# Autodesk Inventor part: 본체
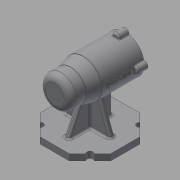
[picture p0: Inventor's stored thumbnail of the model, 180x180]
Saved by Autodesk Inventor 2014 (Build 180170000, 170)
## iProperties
Created: 2019-12
Part Number: 본체
Material: Aluminum 6061
Document SubType Name: Modeling
Designer: kh
Density: 2.71 g/cm^3
Appearance: Default
Mass: 727.794 g
Surface Area: 716.602 cm^2
Volume: 268.559 cm^3
Author: kh
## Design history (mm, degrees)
sketch "Sketch2"
  geometry: L1 (-56, 0)-(56, 0); L2 (-11, 30)-(56, 30); L3 (-56, 25)-(-31, 25); L4 (-31, 25)-(-11, 30); L5 (-56, 25)-(-56, 0); L6 (-13, 24)-(41, 24); L7 (41, 21)-(56, 21); L8 (41, 21)-(41, 24); L9 (56, 21)-(56, 30); L10 (-13, 21)-(-25, 21); L11 (-13, 21)-(-13, 24); L12 (-25, 17.5)-(-43, 17.5); L13 (-25, 17.5)-(-25, 21); L14 (-43, 16)-(-47, 16); L15 (-43, 16)-(-43, 17.5); L16 (-47, 10.5)-(-50, 10.5); L17 (-47, 10.5)-(-47, 16); L18 (-50, 10.5)-(-50, 0); 2 further points
  constraints: 36 end point, 12 perpendicular, 8 vertical alignment, 4 parallel, 2 coincident, 1 horizontal, 1 midpoint, 1 point on line
  dimensions: "d0" = 112 distance of L1.start L1.end; "d1" = 67 distance of L2.start L2.end; "d2" = 60 diameter of L2 L1; "d3" = 25 distance of L3.start L3.end; "d4" = 50 diameter of L3 L1; "d5" = 54 distance of L6.start L6.end; "d6" = 48 diameter of L6 L1; "d7" = 15 distance of L7.start L7.end; "d8" = 42 diameter of L7 L1; "d9" = 12 distance of L10.start L10.end; "d10" = 42 diameter of L10 L1; "d11" = 18 distance of L12.start L12.end; "d12" = 35 diameter of L12 L1; "d14" = 4 distance of L14.start L14.end; "d15" = 32 diameter of L14 L1; "d16" = 3 distance of L16.start L16.end; "d17" = 21 diameter of L16 L1
revolve "Revolution1" sketch "Sketch2" stored, may be unused: angle "d19" = 90 deg
fillet "Fillet1" dims "d22" = 3, "d23" = 0.3
workplane "Work Plane1"
sketch "Sketch4"
  geometry: L1 (0, 0)-(0, 30); C1 r 21 at (0, 0) reference; C2 r 6 at (0, 30); 1 further point
  constraints: 2 end point, 1 centre point, 1 coincident, 1 vertical, 1 vertical alignment, 1 other
  dimensions: "d24" = 12 diameter of C2
extrude "Extrusion2" join sketch "Sketch4" distance "d25" = 16; taper "d26" = 0 deg
fillet "Fillet2" dims "d27" = 3
fillet "Fillet3" dims "d28" = 1
pattern_circular "Circular Pattern1" dims "d30" = 360 deg
hole "Hole1" diameter "d34" = 3.242; stored, may be unused: countersink angle "d38" = 90 deg, drill point angle "d40" = 118 deg; dims "d32" = 10, "d33" = 10, "d35" = 8, "d36" = 4, "d37" = 2, "d39" = 11
pattern_circular "Circular Pattern2" dims angle "d42" = 360 deg
workplane "Work Plane2"
sketch "Sketch5"
  geometry: L1 (-6.771, 56)-(-29.226, 56) reference; L2 (29.226, 56)-(6.771, 56) reference; L3 (23.196, 56)-(56, 23.196); L4 (56, 23.196)-(56, -23.196); L5 (56, -23.196)-(23.196, -56); L6 (23.196, -56)-(-23.196, -56); L7 (-23.196, -56)-(-56, -23.196); L8 (-56, -23.196)-(-56, 23.196); L9 (-56, 23.196)-(-23.196, 56); L10 (-23.196, 56)-(23.196, 56); 2 further points
  constraints: 16 end point, 1 coincident, 1 collinear, 1 horizontal, 17 other
extrude "Extrusion3" join sketch "Sketch5" distance "d45" = 10; taper "d46" = 0 deg
sketch "Sketch6"
  geometry: L1 (56, 23.196)-(23.196, 56) reference; L2 (56, -23.196)-(56, 23.196) reference; L3 (0, 0)-(56, 0); L4 (0, 0)-(39.598, 39.598); C1 r 5 at (39.598, 39.598)
  constraints: 4 end point, 2 midpoint, 1 centre point, 1 coincident, 1 perpendicular
  dimensions: "d47" = 10 diameter of C1
extrude "Extrusion4" cut sketch "Sketch6" stored distance "d48" = 10; taper "d49" = 0 deg
pattern_circular "Circular Pattern3" dims angle "d51" = 360 deg
sketch "Sketch7"
  geometry: L1 (-56, -80)-(-56, -70) reference; L2 (56, -80)-(56, -70) reference; L3 (56, -70)-(43.134, -70) reference; L4 (23.196, -70)-(-23.196, -70) reference; L5 (-43.134, -70)-(-56, -70) reference; L6 (34.598, -70)-(43.134, -70) reference; L7 (36.062, -70)-(23.196, -70) reference; L8 (-43.134, -70)-(-34.598, -70) reference; L9 (-23.196, -70)-(-36.062, -70) reference; L10 (0, 0)-(0, -70); L11 (-36, -70)-(-18.979, -23.234); L12 (36, -70)-(18.979, -23.234); L13 (-36, -70)-(36, -70); A1 r 30 centre (0, 0) between (-18.979, -23.234) and (18.979, -23.234); 1 further point
  constraints: 8 end point, 2 point on circle, 2 symmetric about line, 1 centre point, 1 coincident, 1 collinear, 1 midpoint, 1 point on line, 2 other
  dimensions: "d55" = 110 deg angle of L5 L11; "d56" = 20 distance from line of L11.start L1
extrude "Extrusion5" join sketch "Sketch7" stored distance "d57" = 8; taper "d58" = 0 deg
sketch "Sketch8"
  geometry: L1 (-56, -80)-(-56, -70) reference; L2 (56, -80)-(56, -70) reference; L3 (56, -70)-(43.134, -70) reference; L4 (34.598, -70)-(43.134, -70) reference; L5 (36.062, -70)-(23.196, -70) reference; L6 (23.196, -70)-(-23.196, -70) reference; L7 (-23.196, -70)-(-36.062, -70) reference; L8 (-43.134, -70)-(-56, -70) reference; L9 (-43.134, -70)-(-34.598, -70) reference; L10 (-56, -25)-(-31, -25) reference; L11 (-31, -25)-(-11, -30) reference; L12 (-11, -30)-(39, -30) reference; L13 (-38, -70)-(-18.476, -28.131); L14 (31, -30)-(31, -70); L15 (-18.476, -28.131)-(31, -30); L16 (-38, -70)-(31, -70); 1 further point
  constraints: 8 end point, 4 point on line, 2 perpendicular
  dimensions: "d60" = 115 deg angle of L8 L13; "d61" = 18 distance from line of L1 L13.start; "d62" = 25 distance between parallel lines of L2 L14
extrude "Extrusion6" join sketch "Sketch8" stored distance "d63" = 8; taper "d64" = 0 deg
fillet "Fillet4" dims "d65" = 3, "d66" = 10
fillet "Fillet5" dims "d67" = 3
chamfer "Chamfer1" distance "d68" = 1; stored, may be unused: second distance "d69" = 2, angle "d70" = 45 deg
sketch "Sketch9"
  geometry: L1 (-33.131, 30)-(16.5, 30) reference; L2 (33.5, 6.771)-(33.5, 29.226) reference; L3 (33.5, -29.226)-(33.5, -6.771) reference; 2 further points
  constraints: 1 horizontal alignment, 1 other
  dimensions: "d71" = 41 distance from line of L2 point (-7.5, 0)
emboss "Emboss1" sketch "Sketch9" dims "d1" = 67, "d72" = 0.5, "d73" = 0
body "Solid1"
